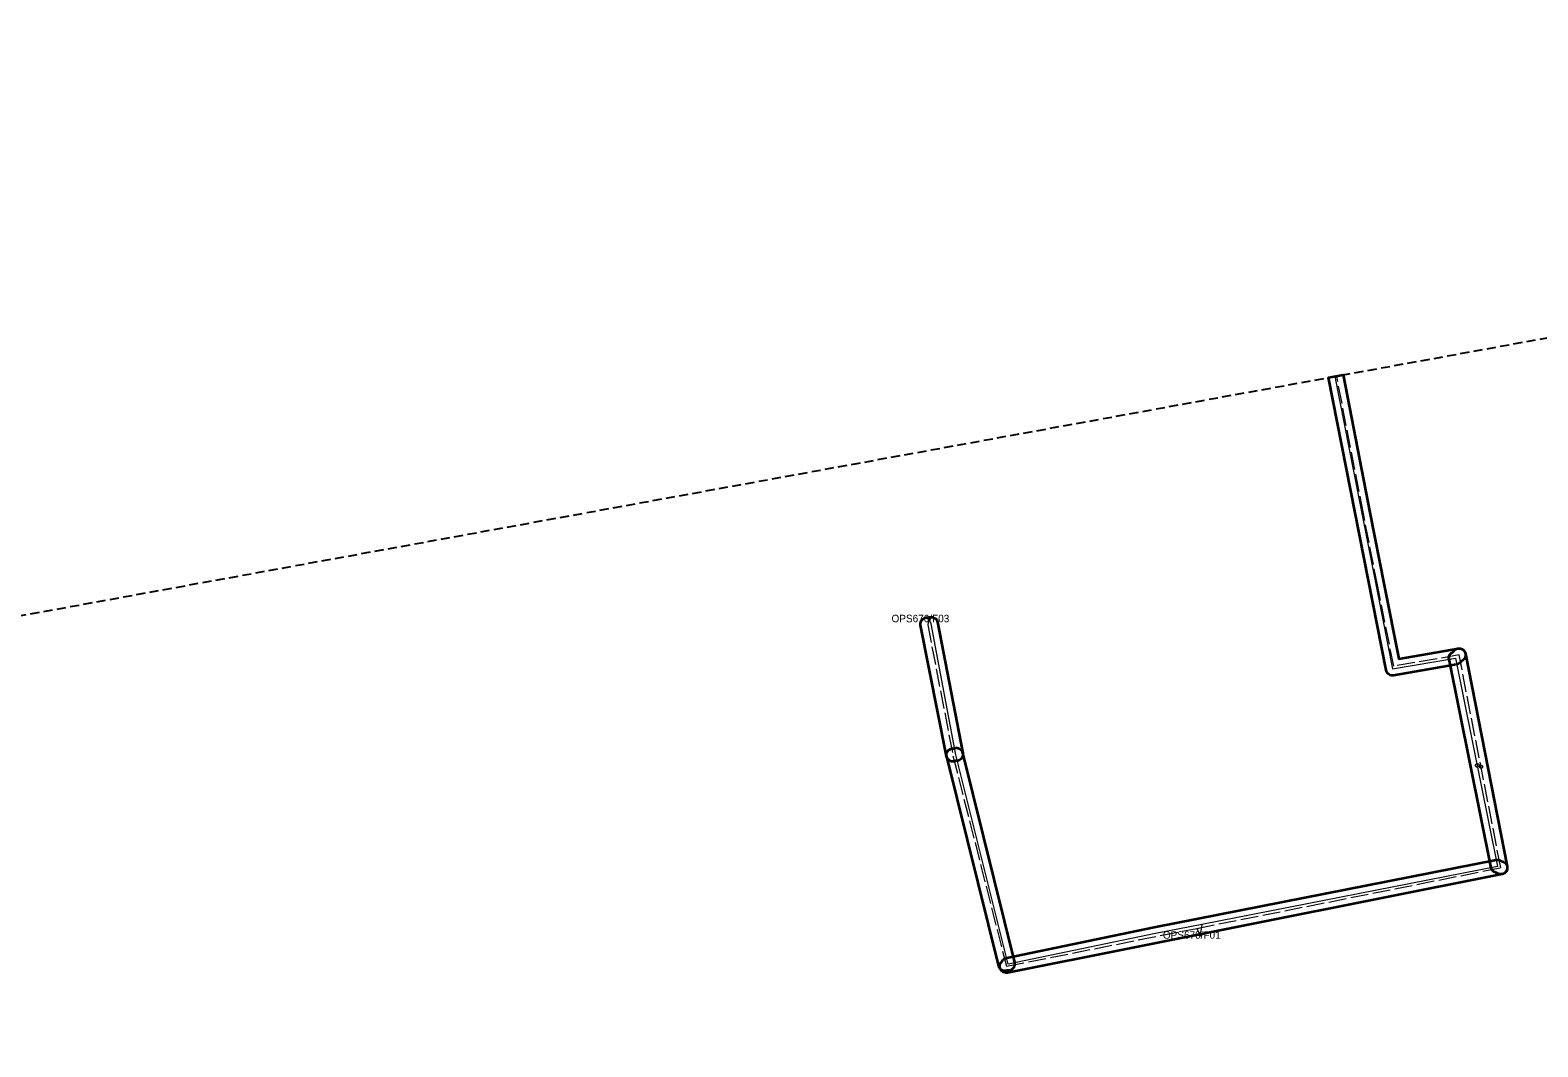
# Model space of a CAD drawing. Extents: x -452602 to -451136, y -1100088 to -1099653.
# Drawn here: x -452078.2 to -451916.9, y -1099870.6 to -1099761.7 of the extents above; entities that cross this region are included whole.
import ezdxf

# ---------------------------------------------------------------- set-up
doc = ezdxf.new("R2010")
doc.units = 0
doc.header["$LTSCALE"] = 0.32
doc.header["$PDMODE"] = 32
doc.header["$PDSIZE"] = 0.16
doc.linetypes.add('LONG_DASHED', pattern=[7.5, 6, -1.5])
doc.linetypes.add('MEDIUM_DASHED', pattern=[4.5, 3, -1.5])
for name, color, linetype, lineweight in [('2', 7, 'Continuous', 13), ('3', 7, 'Continuous', 25), ('62', 7, 'MEDIUM_DASHED', 25), ('8', 7, 'Continuous', 35)]:
    doc.layers.add(name, color=color, linetype=linetype, lineweight=lineweight)
doc.layers.add('4', color=7, linetype='Continuous')

msp = doc.modelspace()

# ---------------------------------------------------------------- linework, layer by layer
at = {"layer": '2', "linetype": 'LONG_DASHED'}
for p, q in [((-451982.025, -1099824.69), (-451982.147, -1099825.366)), ((-451982.147, -1099825.366), (-451979.449, -1099839.379)), ((-451920.839, -1099851.37), (-451925.294, -1099828.591)), ((-451979.449, -1099839.379), (-451973.738, -1099861.929)), ((-451953.37, -1099857.864), (-451920.839, -1099851.37)), ((-451973.738, -1099861.929), (-451953.37, -1099857.864)), ((-451952.991, -1099858.573), (-451953.37, -1099857.864))]:
    msp.add_line(p, q, dxfattribs=at)
at = {"layer": '2'}
for p, q in [((-451981.782, -1099825.278), (-451982.025, -1099824.69)), ((-451979.139, -1099839.286), (-451981.782, -1099825.278)), ((-451925.677, -1099828.922), (-451921.177, -1099851.231)), ((-451973.553, -1099861.695), (-451979.139, -1099839.286)), ((-451921.177, -1099851.231), (-451952.815, -1099857.449)), ((-451952.815, -1099857.449), (-451952.991, -1099858.573))]:
    msp.add_line(p, q, dxfattribs=at)
for points in [[(-451938.575, -1099798.768), (-451932.424, -1099830.086), (-451925.677, -1099828.922)], [(-451952.815, -1099857.449), (-451957.792, -1099858.427), (-451973.553, -1099861.695)]]:
    msp.add_lwpolyline(points, dxfattribs=at)
at = {"layer": '2', "linetype": 'LONG_DASHED'}
msp.add_lwpolyline([(-451925.294, -1099828.591), (-451932.285, -1099829.802), (-451934.006, -1099821.273), (-451935.53, -1099813.463), (-451938.392, -1099798.735)], dxfattribs=at)
at = {"layer": '3', "lineweight": 13}
for points in [[(-451923.358, -1099840.231), (-451923.325, -1099840.234), (-451923.294, -1099840.242), (-451923.264, -1099840.256), (-451923.237, -1099840.275), (-451923.214, -1099840.298), (-451923.195, -1099840.325), (-451923.181, -1099840.355), (-451923.173, -1099840.386), (-451923.17, -1099840.419), (-451923.173, -1099840.452), (-451923.181, -1099840.484), (-451923.195, -1099840.513), (-451923.214, -1099840.54), (-451923.237, -1099840.563), (-451923.264, -1099840.582), (-451923.294, -1099840.596), (-451923.325, -1099840.605), (-451923.358, -1099840.607), (-451923.391, -1099840.605), (-451923.422, -1099840.596), (-451923.452, -1099840.582), (-451923.479, -1099840.563), (-451923.502, -1099840.54), (-451923.521, -1099840.513), (-451923.535, -1099840.484), (-451923.543, -1099840.452), (-451923.546, -1099840.419), (-451923.543, -1099840.386), (-451923.535, -1099840.355), (-451923.521, -1099840.325), (-451923.502, -1099840.298), (-451923.479, -1099840.275), (-451923.452, -1099840.256), (-451923.422, -1099840.242), (-451923.391, -1099840.234)], [(-451922.939, -1099840.395), (-451922.911, -1099840.398), (-451922.883, -1099840.405), (-451922.857, -1099840.417), (-451922.834, -1099840.434), (-451922.814, -1099840.454), (-451922.797, -1099840.477), (-451922.785, -1099840.503), (-451922.778, -1099840.531), (-451922.775, -1099840.559), (-451922.778, -1099840.588), (-451922.785, -1099840.616), (-451922.797, -1099840.642), (-451922.814, -1099840.665), (-451922.834, -1099840.685), (-451922.857, -1099840.702), (-451922.883, -1099840.714), (-451922.911, -1099840.721), (-451922.939, -1099840.724), (-451922.968, -1099840.721), (-451922.996, -1099840.714), (-451923.022, -1099840.702), (-451923.045, -1099840.685), (-451923.065, -1099840.665), (-451923.082, -1099840.642), (-451923.094, -1099840.616), (-451923.101, -1099840.588), (-451923.104, -1099840.559), (-451923.101, -1099840.531), (-451923.094, -1099840.503), (-451923.082, -1099840.477), (-451923.065, -1099840.454), (-451923.045, -1099840.434), (-451923.022, -1099840.417), (-451922.996, -1099840.405), (-451922.968, -1099840.398)]]:
    msp.add_lwpolyline(points, close=True, dxfattribs=at)
at = {"layer": '4'}
for p in [(-451982.025, -1099824.69), (-451952.991, -1099858.573)]:
    msp.add_point(p, dxfattribs=at)
at = {"layer": '62'}
msp.add_lwpolyline([(-451137.485, -1099816.961), (-452572.169, -1100088.267), (-452602.314, -1099919.678), (-451137.485, -1099652.838), (-451136.368, -1099701.963)], close=True, dxfattribs=at)
at = {"layer": '8'}
for points in [[(-451933.32, -1099821.137), (-451931.734, -1099828.996), (-451925.413, -1099827.901), (-451925.292, -1099827.892), (-451925.172, -1099827.904), (-451925.056, -1099827.937), (-451924.946, -1099827.989), (-451924.848, -1099828.059), (-451924.763, -1099828.145), (-451924.694, -1099828.245), (-451924.643, -1099828.354), (-451924.612, -1099828.471), (-451924.601, -1099828.592), (-451924.612, -1099828.712), (-451924.642, -1099828.829), (-451924.693, -1099828.939), (-451924.762, -1099829.039), (-451924.847, -1099829.125), (-451924.945, -1099829.195), (-451925.054, -1099829.247), (-451925.111, -1099829.338), (-451925.182, -1099829.419), (-451925.264, -1099829.489), (-451925.355, -1099829.545), (-451925.454, -1099829.586), (-451925.558, -1099829.612), (-451932.305, -1099830.776), (-451932.425, -1099830.786), (-451932.545, -1099830.776), (-451932.661, -1099830.745), (-451932.77, -1099830.695), (-451932.869, -1099830.626), (-451932.955, -1099830.542), (-451933.025, -1099830.445), (-451933.078, -1099830.337), (-451933.111, -1099830.221), (-451939.264, -1099798.893), (-451937.704, -1099798.609), (-451934.843, -1099813.329)], [(-451981.103, -1099825.098), (-451978.404, -1099839.111), (-451978.391, -1099839.228), (-451978.399, -1099839.345), (-451978.426, -1099839.46), (-451978.471, -1099839.568), (-451978.534, -1099839.667), (-451978.613, -1099839.755), (-451978.705, -1099839.828), (-451978.808, -1099839.884), (-451978.92, -1099839.922), (-451979.035, -1099839.941), (-451979.14, -1099839.942), (-451979.219, -1099839.974), (-451979.301, -1099839.996), (-451979.385, -1099840.008), (-451979.498, -1099840.008), (-451979.609, -1099839.989), (-451979.717, -1099839.953), (-451979.817, -1099839.9), (-451979.907, -1099839.832), (-451979.985, -1099839.75), (-451980.049, -1099839.657), (-451980.097, -1099839.555), (-451980.127, -1099839.446), (-451982.906, -1099825.416), (-451982.918, -1099825.302), (-451982.913, -1099825.188), (-451982.888, -1099825.076), (-451982.846, -1099824.969), (-451982.787, -1099824.871), (-451982.713, -1099824.784), (-451982.626, -1099824.71), (-451982.527, -1099824.651), (-451982.42, -1099824.609), (-451982.309, -1099824.586), (-451982.194, -1099824.58), (-451982.08, -1099824.594), (-451981.972, -1099824.555), (-451981.859, -1099824.534), (-451981.744, -1099824.532), (-451981.631, -1099824.549), (-451981.521, -1099824.584), (-451981.419, -1099824.637), (-451981.327, -1099824.706), (-451981.247, -1099824.789), (-451981.182, -1099824.883), (-451981.134, -1099824.988)], [(-451920.783, -1099852.068), (-451920.886, -1099852.069), (-451920.988, -1099852.054), (-451921.086, -1099852.025), (-451921.18, -1099851.982), (-451921.266, -1099851.925), (-451921.372, -1099851.903), (-451921.474, -1099851.865), (-451921.569, -1099851.811), (-451921.654, -1099851.743), (-451921.728, -1099851.663), (-451921.788, -1099851.573), (-451921.833, -1099851.474), (-451921.863, -1099851.369), (-451926.364, -1099829.06), (-451926.377, -1099828.95), (-451926.372, -1099828.839), (-451926.351, -1099828.73), (-451926.312, -1099828.626), (-451926.257, -1099828.53), (-451926.188, -1099828.443), (-451926.106, -1099828.368), (-451926.013, -1099828.307), (-451925.912, -1099828.262), (-451925.85, -1099828.166), (-451925.773, -1099828.081), (-451925.683, -1099828.009), (-451925.583, -1099827.954), (-451925.475, -1099827.915), (-451925.362, -1099827.894), (-451925.247, -1099827.893), (-451925.134, -1099827.91), (-451925.025, -1099827.945), (-451924.923, -1099827.997), (-451924.831, -1099828.066), (-451924.751, -1099828.148), (-451924.686, -1099828.243), (-451924.638, -1099828.346), (-451924.607, -1099828.457), (-451920.152, -1099851.236), (-451920.139, -1099851.353), (-451920.146, -1099851.471), (-451920.173, -1099851.585), (-451920.218, -1099851.694), (-451920.281, -1099851.793), (-451920.36, -1099851.881), (-451920.452, -1099851.954), (-451920.556, -1099852.01), (-451920.667, -1099852.049)], [(-451978.412, -1099839.076), (-451972.873, -1099861.527), (-451972.854, -1099861.647), (-451972.857, -1099861.768), (-451972.88, -1099861.887), (-451972.923, -1099862), (-451972.985, -1099862.104), (-451973.064, -1099862.196), (-451973.158, -1099862.272), (-451973.263, -1099862.332), (-451973.377, -1099862.372), (-451973.497, -1099862.392), (-451973.57, -1099862.394), (-451973.644, -1099862.389), (-451973.728, -1099862.412), (-451973.814, -1099862.424), (-451973.924, -1099862.424), (-451974.032, -1099862.407), (-451974.136, -1099862.374), (-451974.233, -1099862.325), (-451974.322, -1099862.261), (-451974.4, -1099862.184), (-451974.465, -1099862.096), (-451974.515, -1099861.999), (-451974.549, -1099861.895), (-451980.12, -1099839.479), (-451980.14, -1099839.368), (-451980.141, -1099839.256), (-451980.124, -1099839.144), (-451980.09, -1099839.037), (-451980.039, -1099838.937), (-451979.973, -1099838.846), (-451979.893, -1099838.767), (-451979.802, -1099838.702), (-451979.701, -1099838.652), (-451979.594, -1099838.619), (-451979.482, -1099838.603), (-451979.37, -1099838.606), (-451979.255, -1099838.568), (-451979.135, -1099838.549), (-451979.014, -1099838.552), (-451978.895, -1099838.576), (-451978.782, -1099838.62), (-451978.678, -1099838.682), (-451978.587, -1099838.761), (-451978.511, -1099838.856), (-451978.452, -1099838.962)], [(-451973.682, -1099862.627), (-451973.8, -1099862.627), (-451973.916, -1099862.607), (-451974.028, -1099862.567), (-451974.131, -1099862.509), (-451974.223, -1099862.435), (-451974.301, -1099862.346), (-451974.363, -1099862.246), (-451974.407, -1099862.136), (-451974.432, -1099862.021), (-451974.438, -1099861.903), (-451974.423, -1099861.785), (-451974.389, -1099861.672), (-451974.337, -1099861.566), (-451974.267, -1099861.471), (-451974.182, -1099861.388), (-451974.129, -1099861.296), (-451974.061, -1099861.214), (-451973.983, -1099861.142), (-451973.894, -1099861.083), (-451973.797, -1099861.039), (-451973.695, -1099861.009), (-451957.934, -1099857.742), (-451957.927, -1099857.74), (-451921.312, -1099850.544), (-451921.194, -1099850.531), (-451921.075, -1099850.538), (-451920.96, -1099850.565), (-451920.85, -1099850.612), (-451920.75, -1099850.676), (-451920.637, -1099850.7), (-451920.529, -1099850.743), (-451920.43, -1099850.802), (-451920.342, -1099850.877), (-451920.267, -1099850.966), (-451920.208, -1099851.066), (-451920.167, -1099851.174), (-451920.144, -1099851.288), (-451920.14, -1099851.404), (-451920.155, -1099851.519), (-451920.189, -1099851.629), (-451920.24, -1099851.733), (-451920.308, -1099851.827), (-451920.391, -1099851.908), (-451920.486, -1099851.975), (-451920.59, -1099852.025), (-451920.702, -1099852.057), (-451973.601, -1099862.616), (-451973.608, -1099862.617)]]:
    msp.add_lwpolyline(points, close=True, dxfattribs=at)

# ---------------------------------------------------------------- texts
at = {"layer": '4'}
for s, p in [('OPS670/F03', (-451986.025, -1099825.09)), ('OPS670/F01', (-451956.991, -1099858.973))]:
    msp.add_text(s, height=0.8, dxfattribs=at).set_placement(p)

doc.saveas('drawing.dxf')
